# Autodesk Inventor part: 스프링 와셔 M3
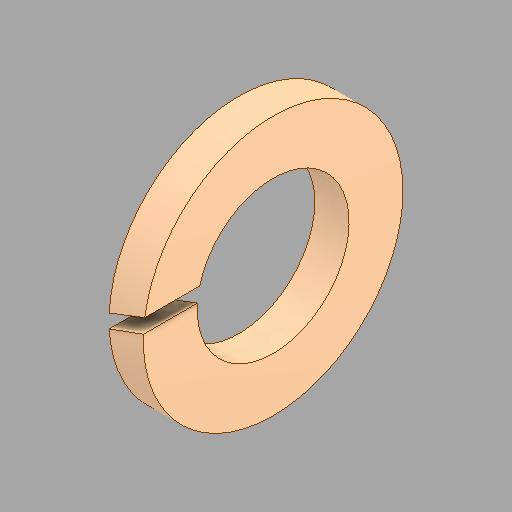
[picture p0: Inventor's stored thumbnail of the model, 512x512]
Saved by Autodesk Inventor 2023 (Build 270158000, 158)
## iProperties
Created: 2025-09
Part Number: 스프링 와셔 M3
Material: 강철, 연강
Description: 스프링 잠금 와셔
Document SubType Name: Modeling
Designer: home
Density: 7.85 g/cm^3
Appearance: 기본값
Author: jhkim
Sending System: Autodesk Inventor 2026
Preprocessor: ST-DEVELOPER v20.1
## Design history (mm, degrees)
feature "Solid1"
node "솔리드1"
